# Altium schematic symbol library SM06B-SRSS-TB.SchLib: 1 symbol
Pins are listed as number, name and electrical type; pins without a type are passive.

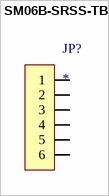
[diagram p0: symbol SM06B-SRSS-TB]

## SM06B-SRSS-TB
designator JP?
Connector Header Surface Mount, Right Angle 6 position 0.039 (1.00mm); MF: JST Sales; MP: SM06B-SRSS-TB
footprint SM06B-SRSS-TB
pins: 1, 2, 3, 4, 5, 6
